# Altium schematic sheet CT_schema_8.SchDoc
size 274 x 160 mm
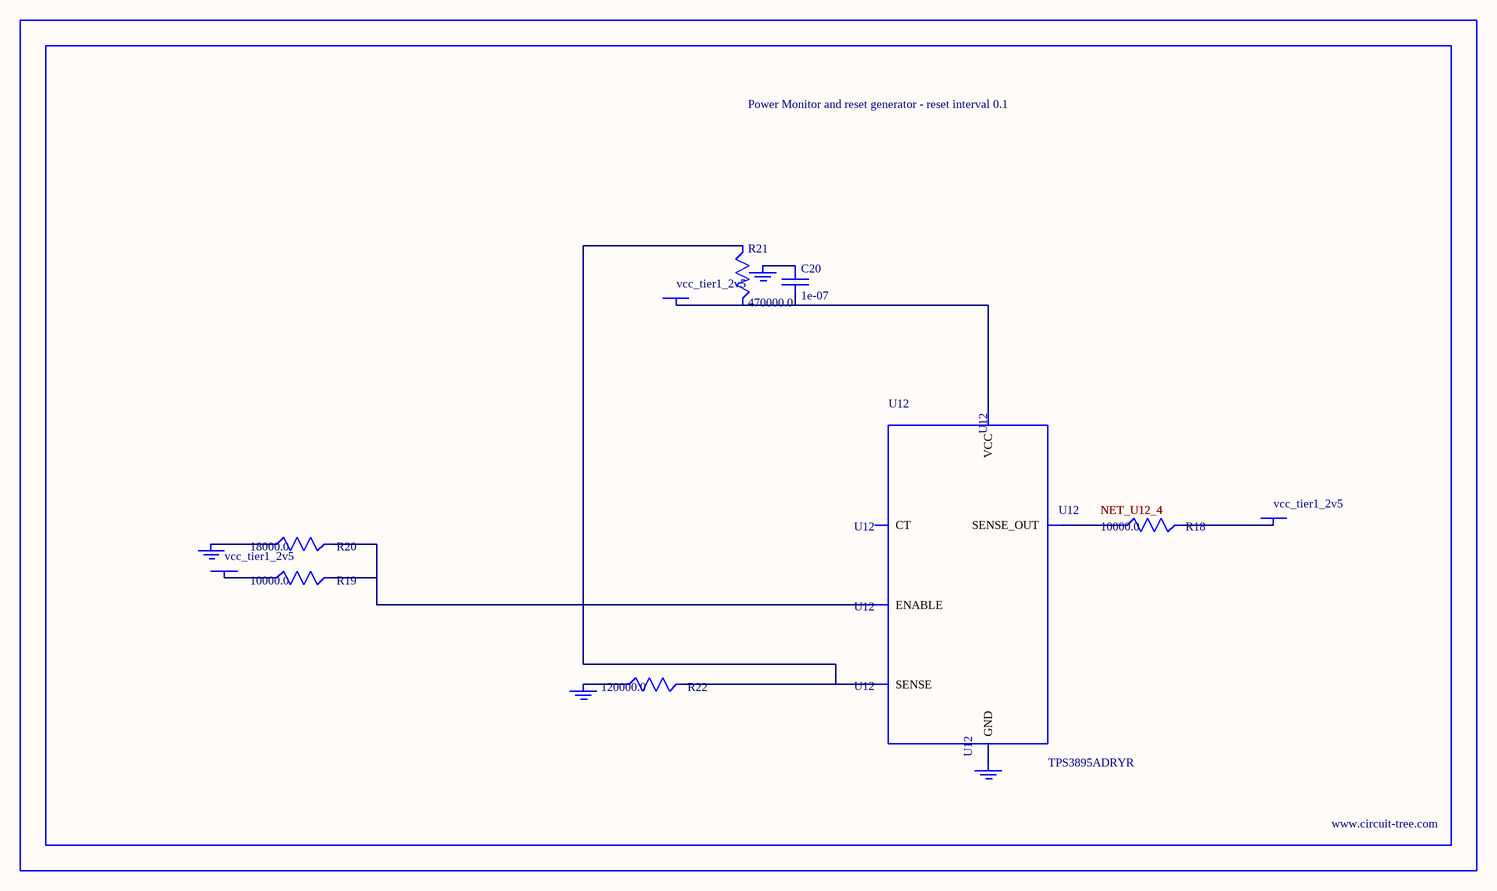
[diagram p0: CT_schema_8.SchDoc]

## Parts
BORDER7  (no value)
C20  1e-07  [C0402]
GND_INSTANCE_7_0  (no value)
GND_INSTANCE_7_1  (no value)
GND_INSTANCE_7_2  (no value)
GND_INSTANCE_7_3  (no value)
POWER_INSTANCE_7_0  vcc_tier1_2v5
POWER_INSTANCE_7_1  vcc_tier1_2v5
POWER_INSTANCE_7_2  vcc_tier1_2v5
R18  10000.0  [R0603]
R19  10000.0  [R0603]
R20  18000.0  [R0603]
R21  470000.0  [R0603]
R22  120000.0  [R0603]
U12  TPS3895ADRYR  [SON-6]

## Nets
NetC20_1: C20.1 GND_INSTANCE_7_2.0(GND)
NetC20_2: C20.2 POWER_INSTANCE_7_2.0(PWR) R21.2 U12.6(VCC)
NetGND_INSTANCE_7_0_0: GND_INSTANCE_7_0.0(GND) R20.1
NetGND_INSTANCE_7_1_0: GND_INSTANCE_7_1.0(GND) R22.1
NetGND_INSTANCE_7_3_0: GND_INSTANCE_7_3.0(GND) U12.2(GND)
NetPOWER_INSTANCE_7_0_0: POWER_INSTANCE_7_0.0(PWR) R19.1
NetPOWER_INSTANCE_7_1_0: POWER_INSTANCE_7_1.0(PWR) R18.2
NetR18_1: R18.1 U12.4(SENSE_OUT)
NetR19_2: R19.2 R20.2 U12.1(ENABLE)
NetR21_1: R21.1 R22.2 U12.3(SENSE)

Not connected (* = marked no-connect by the designer): U12 5(CT)

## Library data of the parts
BORDER7 = BORDER_PAGE7
C20 = C0402C104K3RACTU
GND_INSTANCE_7_0-GND_INSTANCE_7_3 = GND
POWER_INSTANCE_7_0-POWER_INSTANCE_7_2 = PWR
R18 R19 = RC0603JR-0710KL
R20 = RC0603JR-0718KL
R21 = RC0603JR-07470KL
R22 = RC0603JR-07120KL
